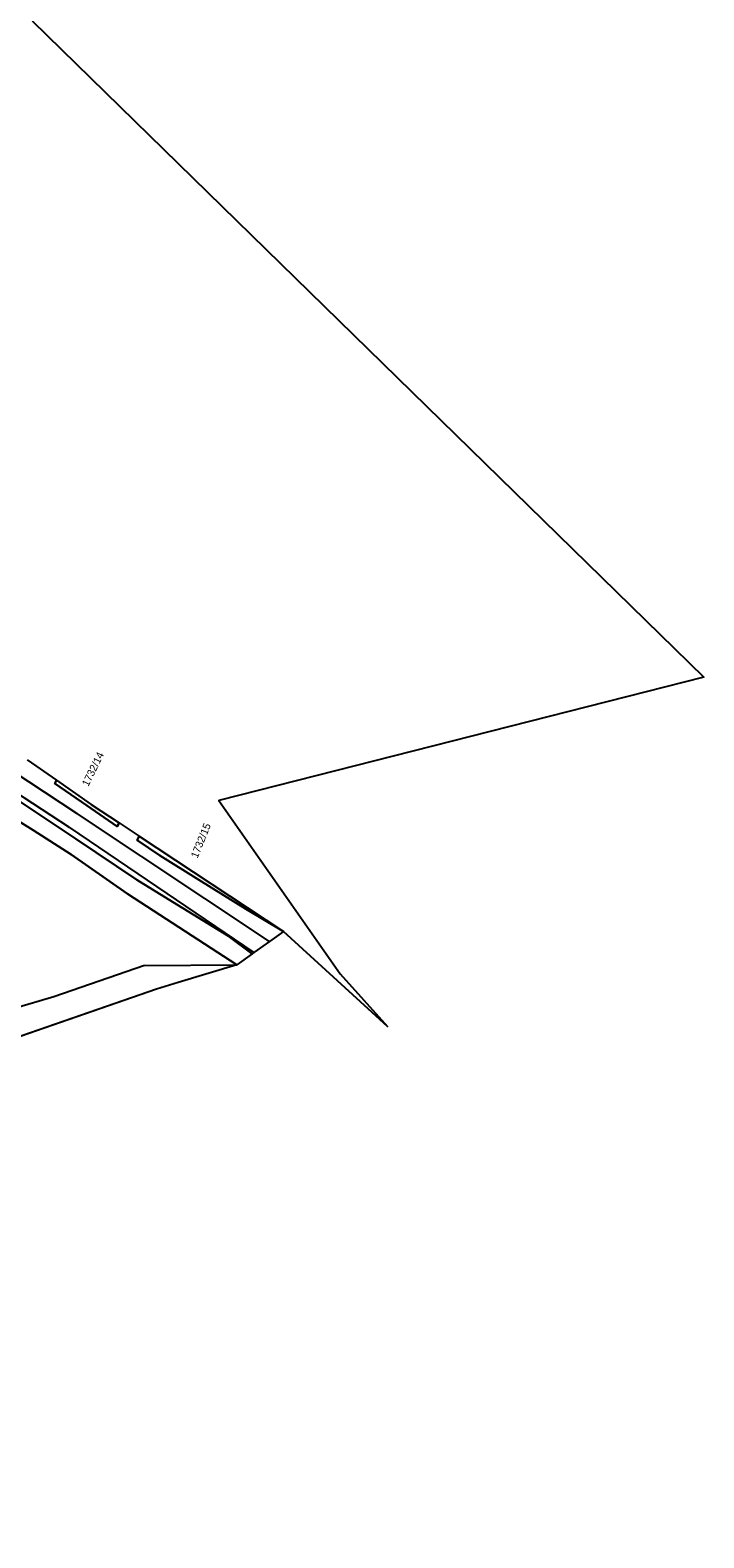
# Model space of a CAD drawing. Extents: x -263943 to -261149, y -1236934 to -1230686.
# Drawn here: x -261901 to -261721.6, y -1236824.8 to -1236423.4 of the extents above; entities that cross this region are included whole.
import ezdxf

# ---------------------------------------------------------------- set-up
doc = ezdxf.new("R2010")
doc.units = 0
for name, color, linetype in [('body_kn', 7, 'Continuous'), ('kladpar_druhypozemkov', 7, 'Continuous'), ('kladpar_hranice', 7, 'Continuous'), ('kladpar_parcelnecisla', 7, 'Continuous'), ('kladpar_plochy', 7, 'Continuous'), ('kladpar_sipky', 7, 'Continuous'), ('zappar_hrandruhpozemk', 7, 'Continuous'), ('zuob_linie', 7, 'Continuous'), ('zuob_plochy', 7, 'Continuous')]:
    doc.layers.add(name, color=color, linetype=linetype)

msp = doc.modelspace()

# ---------------------------------------------------------------- linework, layer by layer
at = {"layer": 'body_kn'}
for p, q in [((-261721.65, -1236595.68), (-261721.65, -1236595.68)), ((-261894.44, -1236624.01), (-261894.44, -1236624.01)), ((-261894.01, -1236623.11), (-261894.01, -1236623.11)), ((-261894.01, -1236623.11), (-261894.01, -1236623.11)), ((-261850.8, -1236628.52), (-261850.8, -1236628.52)), ((-261888.66, -1236631.88), (-261888.66, -1236631.88)), ((-261885.91, -1236629.87), (-261885.91, -1236629.87)), ((-261884.76, -1236629.56), (-261884.76, -1236629.56)), ((-261900.28, -1236636.43), (-261900.28, -1236636.43)), ((-261890.53, -1236635.68), (-261890.53, -1236635.68)), ((-261877.83, -1236635.42), (-261877.83, -1236635.42)), ((-261877.36, -1236634.45), (-261877.36, -1236634.45)), ((-261888.92, -1236638.74), (-261888.92, -1236638.74)), ((-261872.55, -1236639.05), (-261872.55, -1236639.05)), ((-261872.03, -1236637.97), (-261872.03, -1236637.97)), ((-261872.03, -1236637.97), (-261872.03, -1236637.97)), ((-261890.12, -1236642.89), (-261890.12, -1236642.89)), ((-261866.53, -1236643.18), (-261866.53, -1236643.18)), ((-261872.65, -1236649.63), (-261872.65, -1236649.63)), ((-261856.16, -1236649.6), (-261856.16, -1236649.6)), ((-261875.14, -1236653.34), (-261875.14, -1236653.34)), ((-261875.14, -1236653.34), (-261875.14, -1236653.34)), ((-261863.13, -1236655.48), (-261863.13, -1236655.48)), ((-261843.67, -1236657.35), (-261843.67, -1236657.35)), ((-261848.2, -1236664.66), (-261848.2, -1236664.66)), ((-261833.57, -1236663.38), (-261833.57, -1236663.38)), ((-261833.57, -1236663.38), (-261833.57, -1236663.38)), ((-261841.46, -1236668.99), (-261841.46, -1236668.99)), ((-261837.31, -1236666.04), (-261837.31, -1236666.04)), ((-261837.31, -1236666.04), (-261837.31, -1236666.04)), ((-261870.57, -1236672.4), (-261870.57, -1236672.4)), ((-261846.03, -1236672.24), (-261846.03, -1236672.24)), ((-261841.94, -1236669.33), (-261841.94, -1236669.33)), ((-261841.94, -1236669.33), (-261841.94, -1236669.33)), ((-261861.65, -1236676.99), (-261861.65, -1236676.99)), ((-261818.47, -1236674.69), (-261818.47, -1236674.69)), ((-261894.76, -1236680.74), (-261894.76, -1236680.74)), ((-261894.76, -1236680.74), (-261894.76, -1236680.74)), ((-261867.4, -1236678.73), (-261867.4, -1236678.73)), ((-261805.93, -1236688.64), (-261805.93, -1236688.64))]:
    msp.add_line(p, q, dxfattribs=at)
at = {"layer": 'kladpar_druhypozemkov'}
for p, q in [((-261883.53, -1236630.85), (-261883.53, -1236630.85)), ((-261864.73, -1236643.56), (-261864.73, -1236643.56))]:
    msp.add_line(p, q, dxfattribs=at)
at = {"layer": 'kladpar_hranice'}
for p, q in [((-261901.81, -1236617.67), (-261894.01, -1236623.11)), ((-261877.36, -1236634.45), (-261872.03, -1236637.97)), ((-261872.03, -1236637.97), (-261833.57, -1236663.38)), ((-261890.12, -1236642.89), (-261875.14, -1236653.34))]:
    msp.add_line(p, q, dxfattribs=at)
for points in [[(-261875.14, -1236653.34), (-261846.03, -1236672.24), (-261861.65, -1236676.99), (-261867.4, -1236678.73), (-262126.94, -1236768.63), (-262127.52, -1236767.4), (-262047.76, -1236739.78), (-261966.17, -1236711.44), (-261945.82, -1236704.45), (-261948.27, -1236697.22), (-261958.56, -1236666.9), (-261961.77, -1236657.32), (-261974.17, -1236623.23), (-261975.59, -1236609.76), (-261962.77, -1236601.65), (-261946.58, -1236601.68), (-261931.27, -1236617.05), (-261900.28, -1236636.43), (-261890.12, -1236642.89)], [(-261841.94, -1236669.33), (-261846.03, -1236672.24), (-261875.14, -1236653.34), (-261890.12, -1236642.89), (-261900.28, -1236636.43), (-261931.27, -1236617.05)], [(-261894.01, -1236623.11), (-261894.44, -1236624.01), (-261885.91, -1236629.87), (-261877.83, -1236635.42), (-261877.36, -1236634.45)], [(-261877.36, -1236634.45), (-261877.83, -1236635.42), (-261885.91, -1236629.87), (-261894.44, -1236624.01), (-261894.01, -1236623.11)], [(-261894.01, -1236623.11), (-261884.76, -1236629.56), (-261877.36, -1236634.45)], [(-261841.94, -1236669.33), (-261848.2, -1236664.66), (-261863.13, -1236655.48), (-261872.65, -1236649.63), (-261888.92, -1236638.74), (-261904.59, -1236628.26)], [(-261904.59, -1236628.26), (-261888.92, -1236638.74), (-261872.65, -1236649.63), (-261863.13, -1236655.48), (-261848.2, -1236664.66), (-261841.94, -1236669.33)], [(-261872.03, -1236637.97), (-261872.55, -1236639.05), (-261866.53, -1236643.18), (-261856.16, -1236649.6), (-261843.67, -1236657.35), (-261833.57, -1236663.38)], [(-261833.57, -1236663.38), (-261843.67, -1236657.35), (-261856.16, -1236649.6), (-261866.53, -1236643.18), (-261872.55, -1236639.05), (-261872.03, -1236637.97)], [(-261833.57, -1236663.38), (-261837.31, -1236666.04), (-261841.46, -1236668.99), (-261841.94, -1236669.33)]]:
    msp.add_lwpolyline(points, dxfattribs=at)
at = {"layer": 'kladpar_plochy'}
for p, q in [((-261931.27, -1236617.05), (-261900.28, -1236636.43)), ((-261900.28, -1236636.43), (-261890.12, -1236642.89)), ((-261890.12, -1236642.89), (-261875.14, -1236653.34)), ((-261875.14, -1236653.34), (-261846.03, -1236672.24)), ((-261846.03, -1236672.24), (-261861.65, -1236676.99)), ((-261861.65, -1236676.99), (-261867.4, -1236678.73)), ((-261867.4, -1236678.73), (-262126.94, -1236768.63))]:
    msp.add_line(p, q, dxfattribs=at)
for points in [[(-261904.59, -1236628.26), (-261888.92, -1236638.74), (-261872.65, -1236649.63), (-261863.13, -1236655.48), (-261848.2, -1236664.66), (-261841.94, -1236669.33), (-261846.03, -1236672.24), (-261875.14, -1236653.34), (-261890.12, -1236642.89), (-261900.28, -1236636.43), (-261931.27, -1236617.05)], [(-261901.81, -1236617.67), (-261894.01, -1236623.11), (-261894.44, -1236624.01), (-261885.91, -1236629.87), (-261877.83, -1236635.42), (-261877.36, -1236634.45), (-261872.03, -1236637.97), (-261872.55, -1236639.05), (-261866.53, -1236643.18), (-261856.16, -1236649.6), (-261843.67, -1236657.35), (-261833.57, -1236663.38), (-261837.31, -1236666.04), (-261841.46, -1236668.99), (-261841.94, -1236669.33), (-261848.2, -1236664.66), (-261863.13, -1236655.48), (-261872.65, -1236649.63), (-261888.92, -1236638.74), (-261904.59, -1236628.26)]]:
    msp.add_lwpolyline(points, dxfattribs=at)
for points in [[(-261894.01, -1236623.11), (-261884.76, -1236629.56), (-261877.36, -1236634.45), (-261877.83, -1236635.42), (-261885.91, -1236629.87), (-261894.44, -1236624.01)], [(-261872.03, -1236637.97), (-261833.57, -1236663.38), (-261843.67, -1236657.35), (-261856.16, -1236649.6), (-261866.53, -1236643.18), (-261872.55, -1236639.05)]]:
    msp.add_lwpolyline(points, close=True, dxfattribs=at)
at = {"layer": 'kladpar_sipky'}
for p, q in [((-261888.8, -1236626.94), (-261888.8, -1236626.94)), ((-261859.65, -1236646.29), (-261859.65, -1236646.29))]:
    msp.add_line(p, q, dxfattribs=at)
at = {"layer": 'zappar_hrandruhpozemk'}
for p, q in [((-261925.82, -1236607.4), (-261888.66, -1236631.88)), ((-261890.53, -1236635.68), (-261928.46, -1236610.95)), ((-261837.31, -1236666.04), (-261888.66, -1236631.88)), ((-261890.53, -1236635.68), (-261841.46, -1236668.99)), ((-261870.57, -1236672.4), (-261894.76, -1236680.74)), ((-261870.57, -1236672.4), (-261846.03, -1236672.24)), ((-261894.76, -1236680.74), (-261917.06, -1236687.39))]:
    msp.add_line(p, q, dxfattribs=at)
at = {"layer": 'zuob_linie'}
msp.add_lwpolyline([(-261900.47, -1236420.93), (-261721.65, -1236595.68), (-261850.8, -1236628.52), (-261818.47, -1236674.69), (-261805.93, -1236688.64), (-261833.57, -1236663.38), (-261837.31, -1236666.04), (-261841.46, -1236668.99), (-261841.94, -1236669.33), (-261846.03, -1236672.24), (-261861.65, -1236676.99), (-261867.4, -1236678.73), (-262126.94, -1236768.63), (-262129.29, -1236769.44), (-262203.07, -1236794.45), (-262292.7, -1236824.82)], dxfattribs=at)
at = {"layer": 'zuob_plochy'}
msp.add_lwpolyline([(-261900.47, -1236420.93), (-261721.65, -1236595.68), (-261850.8, -1236628.52), (-261818.47, -1236674.69), (-261805.93, -1236688.64), (-261833.57, -1236663.38), (-261837.31, -1236666.04), (-261841.46, -1236668.99), (-261841.94, -1236669.33), (-261846.03, -1236672.24), (-261861.65, -1236676.99), (-261867.4, -1236678.73), (-262126.94, -1236768.63), (-262129.29, -1236769.44), (-262203.07, -1236794.45), (-262292.7, -1236824.82)], dxfattribs=at)

# ---------------------------------------------------------------- texts
at = {"layer": 'kladpar_parcelnecisla'}
for s, rotation, p in [('1732/14', 64, (-261885.56, -1236624.93)), ('1732/15', 68, (-261856.49, -1236644.03))]:
    msp.add_text(s, height=2, rotation=rotation, dxfattribs=at).set_placement(p)

doc.saveas('drawing.dxf')
